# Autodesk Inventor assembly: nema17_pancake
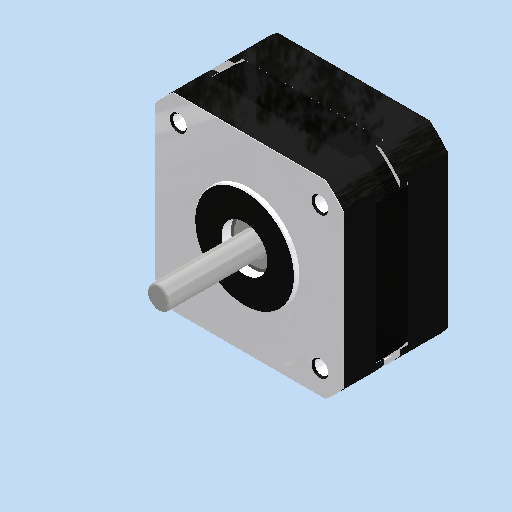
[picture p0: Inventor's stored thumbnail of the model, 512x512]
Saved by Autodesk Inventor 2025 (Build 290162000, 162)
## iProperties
Company: Unknown
Created: 2025-03
Part Number: nema17_pancake
Description: Unknown
Document SubType Name: Assembly
Designer: R5800u
Authority: Unknown
Title: nema17_pancake
Author: Unknown
Sending System: Solid Edge
Preprocessor: ST-DEVELOPER v19.4
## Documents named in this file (8)
- C:\Users\R5800u\Desktop\drone\nema17_compatto\nema17_pancake\nema17_pancake.iam
- C:\Users\R5800u\Desktop\drone\nema17_compatto\nema17_pancake\back_plate.ipt
- C:\Users\R5800u\Desktop\drone\nema17_compatto\nema17_pancake\front_plate.ipt
- C:\Users\R5800u\Desktop\drone\nema17_compatto\nema17_pancake\stator.ipt
- C:\Users\R5800u\Desktop\drone\nema17_compatto\nema17_pancake\625ZZ.ipt
- C:\Users\R5800u\Desktop\drone\nema17_compatto\nema17_pancake\rotor.ipt
- C:\Users\R5800u\Desktop\drone\nema17_compatto\nema17_pancake\connector.ipt
- C:\Users\R5800u\Desktop\drone\nema17_compatto\nema17_pancake\M3_screw.ipt
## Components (11 placed, 7 different names)
1. back_plate
2. front_plate
3. stator
4. 625ZZ
5. 625ZZ:1
6. rotor
7. connector
8. M3_screw
9. M3_screw:1
10. M3_screw:2
11. M3_screw:3
